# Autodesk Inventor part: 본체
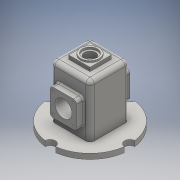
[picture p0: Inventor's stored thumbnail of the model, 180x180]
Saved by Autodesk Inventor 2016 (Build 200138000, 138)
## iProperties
Created: 2018-07
Part Number: 본체
Material: 일반
Document SubType Name: Modeling
Designer: 2-PC07
Density: 1 g/cm^3
Appearance: 기본값
Author: 2-PC07
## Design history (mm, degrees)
sketch "스케치1"
  geometry: C1 r 75 at (0, 0); 1 further point
  constraints: 1 centre point, 1 coincident
  dimensions: "d0" = 150 diameter of C1
extrude "돌출1" new body sketch "스케치1" distance "d1" = 10; taper "d2" = 0 deg
sketch "스케치2"
  geometry: L1 (-37, -37)-(37, -37); L2 (37, -37)-(37, 37); L3 (37, 37)-(-37, 37); L4 (-37, 37)-(-37, -37); L5 (-37, -37)-(37, 37); L6 (37, -37)-(-37, 37); 1 further point
  constraints: 12 end point, 2 midpoint, 2 parallel, 1 horizontal, 1 perpendicular
  dimensions: "d3" = 74 distance of L3.end L2.end; "d4" = 74 distance of L1.end L2.end
extrude "돌출2" join sketch "스케치2" distance "d5" = 100; taper "d6" = 0 deg
sketch "스케치3"
  geometry: L1 (-20, -20)-(20, -20); L2 (20, -20)-(20, 20); L3 (20, 20)-(-20, 20); L4 (-20, 20)-(-20, -20); L5 (-20, -20)-(20, 20); L6 (20, -20)-(-20, 20); 1 further point
  constraints: 12 end point, 2 midpoint, 2 parallel, 1 horizontal, 1 perpendicular
  dimensions: "d7" = 40 distance of L3.end L2.end; "d8" = 40 distance of L2.end L1.end
extrude "돌출3" join sketch "스케치3" distance "d9" = 7; taper "d10" = 0 deg
sketch "스케치4"
  geometry: C1 r 17.5 at (0, 0); 1 further point
  constraints: 1 centre point, 1 coincident
  dimensions: "d11" = 35 diameter of C1
extrude "돌출4" join sketch "스케치4" distance "d12" = 3; taper "d13" = 0 deg
sketch "스케치5"
  geometry: L1 (32, -32)-(-32, -32); L2 (-32, -32)-(-32, 32); L3 (-32, 32)-(32, 32); L4 (32, 32)-(32, -32); L5 (32, -32)-(-32, 32); L6 (-32, -32)-(32, 32); 1 further point
  constraints: 12 end point, 2 midpoint, 2 parallel, 1 horizontal, 1 perpendicular
  dimensions: "d14" = 64 distance of L2.end L3.end; "d15" = 64 distance of L1.end L2.end
extrude "돌출5" cut sketch "스케치5" distance "d16" = 105; taper "d17" = 0 deg
sketch "스케치6"
  geometry: L1 (74, 0)-(0, 0) reference; L2 (74, 0)-(74, 100) reference; L3 (0, 100)-(74, 100) reference; L4 (0, 0)-(0, 100) reference; L5 (12, 20)-(62, 20); L6 (62, 20)-(62, 70); L7 (62, 70)-(12, 70); L8 (12, 70)-(12, 20); L9 (12, 20)-(62, 70); L10 (62, 20)-(12, 70); L11 (5, -10)-(69, -10) reference; 2 further points
  constraints: 12 end point, 2 midpoint, 2 parallel, 1 horizontal, 1 perpendicular
  dimensions: "d18" = 50 distance of L7.end L6.end; "d19" = 50 distance of L6.end L5.end; "d20" = 55 distance of point (37, -10) point (37, 45); "d21" = 37 distance from line of point (37, 45) L2
extrude "돌출6" join sketch "스케치6" distance "d22" = 13; taper "d23" = 0 deg
sketch "스케치7"
  geometry: L1 (-32, 0)-(-32, 105) reference; L2 (-32, 80)-(-25, 77.452); L3 (-25, 77.452)-(-25, 55); L4 (-37, 80)-(-50, 80) reference; L5 (-25, 55)-(-32, 55); L6 (-32, 80)-(-32, 55); L7 (-50, 80)-(-50, 30) reference; 2 further points
  constraints: 8 end point, 3 point on line, 2 perpendicular, 1 collinear, 1 midpoint
  dimensions: "d24" = 7 horizontal distance of L2.start L2.end; "d25" = 50 diameter of L2.start L5; "d26" = 110 deg angle of L1 L2
revolve "회전1" sketch "스케치7" stored, may be unused: angle "d27" = 90 deg
sketch "스케치8"
  geometry: C1 r 10 at (-75, 0); C2 r 10 at (0, 75); C3 r 10 at (75, 0); C4 r 10 at (0, -75); A1 r 75 centre (0, 0) between (-75, 0) and (0, 75) reference; A2 r 75 centre (0, 0) between (0, 75) and (75, 0) reference; 1 further point
  constraints: 7 point on circle, 4 centre point, 3 equal radius, 2 horizontal alignment, 2 vertical alignment
  dimensions: "d29" = 10 radius of C1
extrude "돌출7" cut sketch "스케치8" stored distance "d30" = 13; taper "d31" = 0 deg
sketch "스케치9"
  geometry: L1 (74, 0)-(74, 100) reference; C1 r 16 at (37, 45); 1 further point
  constraints: 1 centre point
  dimensions: "d32" = 32 diameter of C1; "d33" = 37 distance from line of L1 C1.centre; "d34" = 55 distance of point (37, -10) C1.centre
extrude "돌출8" cut sketch "스케치9" stored distance "d35" = 13; taper "d36" = 0 deg
hole "구멍1" diameter "d39" = 21; stored, may be unused: countersink angle "d43" = 90 deg, drill point angle "d45" = 118 deg; dims "d37" = 10, "d38" = 10, "d40" = 6, "d41" = 28, "d42" = 4, "d44" = 8
sketch "스케치10"
  geometry: L1 (62, 70)-(12, 70) reference; L2 (12, 70)-(12, 20) reference; L3 (12, 20)-(62, 20) reference; L4 (62, 20)-(62, 70) reference; 5 further points
  constraints: 2 horizontal alignment, 2 vertical alignment
  dimensions: "d46" = 6 distance from line of L1 point (18, 64); "d47" = 6 distance from line of L2 point (18, 64); "d48" = 6 distance from line of L3 point (18, 26); "d49" = 6 distance from line of L4 point (56, 26)
hole "구멍2" sketch "스케치10" at (18, 64), (18, 26), (56, 26), (56, 64) diameter "d50" = 3.242; stored, may be unused: countersink angle "d54" = 90 deg, drill point angle "d56" = 118 deg; dims "d51" = 8, "d52" = 28, "d53" = 4, "d55" = 10
fillet "모깎기1" dims "d57" = 8
fillet "모깎기2" dims "d58" = 3, "d59" = 6
node "솔리드1"
mirror "대칭1"
mirror "대칭2"
mirror "대칭3"
node "투영된 루프1"
